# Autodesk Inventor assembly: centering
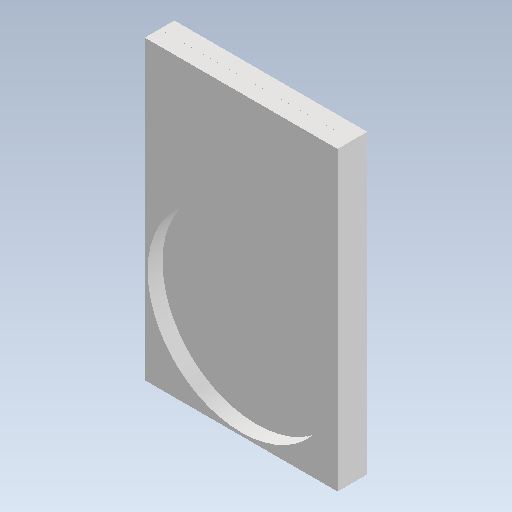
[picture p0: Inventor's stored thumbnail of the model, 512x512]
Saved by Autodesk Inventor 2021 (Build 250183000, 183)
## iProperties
Created: 2026-10
Part Number: centering
Document SubType Name: Assembly
Designer: alolo
Author: alolo
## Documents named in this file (3)
- C:\Users\alolo\Documents\Inventor\Design 1\centering.iam
- C:\Users\alolo\Documents\Inventor\Design 1\centering_base.ipt
- C:\Users\alolo\Documents\Inventor\Design 1\centering_bore.ipt
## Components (2 placed, 2 different names)
1. centering_base:1 — Mate:1, Mate:2, Mate:3
2. centering_bore:1 — Mate:1, Mate:2, Mate:3
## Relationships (3: Mate 3)
- Mate:1: centering_base:1 ↔ centering_bore:1
- Mate:2: centering_base:1 ↔ centering_bore:1
- Mate:3: centering_base:1 ↔ centering_bore:1
